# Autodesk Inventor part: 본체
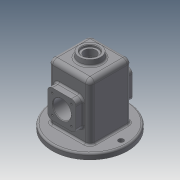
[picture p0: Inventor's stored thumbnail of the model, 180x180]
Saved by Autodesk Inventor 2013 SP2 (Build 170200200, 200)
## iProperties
Created: 2021-08
Part Number: 본체
Material: Generic
Document SubType Name: Modeling
Designer: kumcom13
Density: 1 g/cm^3
Author: kumcom13
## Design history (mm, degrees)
sketch "스케치1"
  geometry: L1 (-37, -55)-(37, -55); L2 (37, -55)-(37, 55); L3 (37, 55)-(-37, 55); L4 (-37, 55)-(-37, -55); L5 (-37, -55)-(37, 55); L6 (37, -55)-(-37, 55); 1 further point
  constraints: 12 end point, 2 midpoint, 2 parallel, 1 horizontal, 1 perpendicular
  dimensions: "d0" = 74 distance of L3.end L2.end; "d1" = 110 distance of L2.end L1.end
extrude "돌출1" new body sketch "스케치1" stored distance "d2" = 74; taper "d3" = 0 deg
feature "쉘1" dims "d4" = 5
sketch "스케치3"
  geometry: L1 (74, -74)-(74, 0) reference; L2 (0, 0)-(74, 0) reference; L3 (0, 0)-(0, -74) reference; L4 (74, -74)-(0, -74) reference; C1 r 67 at (37, -37); 1 further point
  constraints: 1 centre point, 1 coincident
  dimensions: "d5" = 134 diameter of C1
extrude "돌출2" join sketch "스케치3" distance "d6" = 10; taper "d7" = 0 deg
sketch "스케치4"
  geometry: C1 r 20 at (37, 37); 1 further point
  constraints: 1 centre point, 1 coincident
  dimensions: "d8" = 40 diameter of C1
extrude "돌출3" join sketch "스케치4" distance "d9" = 10; taper "d10" = -6 deg
sketch "스케치5"
  geometry: C1 r 18.949 at (0, 0) reference; 1 further point
  constraints: 1 coincident
hole "구멍1" sketch "스케치5" at (0, 0) diameter "d11" = 21; stored, may be unused: countersink angle "d15" = 90 deg, drill point angle "d17" = 0 deg; dims "d12" = 6, "d13" = 28, "d14" = 4, "d16" = 15
sketch "스케치6"
  geometry: L1 (67, -55)-(-67, -55) reference; L2 (-25, -25)-(25, -25); L3 (25, -25)-(25, 25); L4 (25, 25)-(-25, 25); L5 (-25, 25)-(-25, -25); L6 (-25, -25)-(25, 25); L7 (25, -25)-(-25, 25); 1 further point
  constraints: 12 end point, 2 midpoint, 2 parallel, 1 horizontal, 1 perpendicular
  dimensions: "d18" = 50 distance of L4.end L3.end; "d19" = 50 distance of L3.end L2.end
extrude "돌출4" join sketch "스케치6" distance "d20" = 13; taper "d21" = 0 deg
fillet "모깎기1" dims "d22" = 8
sketch "스케치7"
  geometry: C1 r 16 at (0, 0); 1 further point
  constraints: 1 centre point, 1 coincident
  dimensions: "d23" = 32 diameter of C1
extrude "돌출5" cut sketch "스케치7" stored distance "d24" = 13; taper "d25" = 0 deg
sketch "스케치8"
  geometry: A1 r 8 centre (-17, 17) between (-17, 25) and (-25, 17) reference; A2 r 8 centre (-17, -17) between (-25, -17) and (-17, -25) reference; A3 r 8 centre (17, -17) between (17, -25) and (25, -17) reference; A4 r 8 centre (17, 17) between (25, 17) and (17, 25) reference; 4 further points
  constraints: 4 coincident
hole "구멍2" sketch "스케치8" at (-17, 17), (17, 17), (17, -17), (-17, -17) diameter "d26" = 3.242; stored, may be unused: countersink angle "d30" = 90 deg, drill point angle "d32" = 118 deg; dims "d27" = 8, "d28" = 28, "d29" = 4, "d31" = 10
chamfer "모따기1" distance "d33" = 1; stored, may be unused: second distance "d34" = 2, angle "d35" = 45 deg
fillet "모깎기2" dims "d36" = 8
fillet "모깎기3" dims "d37" = 8
fillet "모깎기4" dims "d38" = 3
fillet "모깎기5" dims "d39" = 3
chamfer "모따기2" distance "d40" = 1; stored, may be unused: second distance "d41" = 2, angle "d42" = 45 deg
sketch "스케치9"
  geometry: L1 (40, -29)-(40, 29) reference; L2 (0, 0)-(-55, 0); L3 (0, 0)-(55, 0); C1 r 64 at (0, 0) reference; C2 r 4.5 at (-55, 0); C3 r 4.5 at (55, 0)
  constraints: 4 end point, 2 centre point, 2 coincident, 1 collinear, 1 perpendicular
  dimensions: "d43" = 55 distance of L2.start L2.end; "d44" = 55 distance of L2.start L3.end; "d45" = 9 diameter of C2; "d46" = 9 diameter of C3
extrude "돌출6" cut sketch "스케치9" stored distance "d47" = 13; taper "d48" = 0 deg
fillet "모깎기6" dims "d49" = 3
fillet "모깎기7" dims "d50" = 3
node "작업 평면1"
node "작업 평면2"
sketch "스케치12"
  geometry: L1 (-18.949, 65)-(18.949, 65) reference; L2 (-37, 47)-(-37, -42) reference; 2 further points
  constraints: 1 other
  dimensions: "d58" = 28 distance from line of point (0, 37) L1; "d59" = 37 distance from line of point (0, 37) L2
feature "엠보싱1" sketch "스케치12" dims "d0" = 74, "d1" = 110, "d60" = 0.5, "d61" = 0
sketch "스케치13"
  geometry: C1 r 16 at (29, 55) reference; C2 r 25 at (29, 55)
  constraints: 1 centre point, 1 coincident
  dimensions: "d62" = 50 diameter of C2
extrude "돌출9" join sketch "스케치13" distance "d63" = 7; taper "d64" = -20 deg
sketch "스케치14"
  geometry: C1 r 16 at (0, 0) reference; C2 r 16 at (0, 0)
  constraints: 1 centre point, 1 coincident
  dimensions: "d65" = 32 diameter of C2
extrude "돌출10" cut sketch "스케치14" distance "d66" = 100; taper "d67" = 0 deg
node "솔리드1"
mirror "대칭1"
mirror "대칭3"
other parameters: "d51" = -25
